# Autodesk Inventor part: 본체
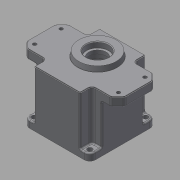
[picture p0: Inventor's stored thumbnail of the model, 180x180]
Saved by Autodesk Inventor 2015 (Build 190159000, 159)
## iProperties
Created: 2016-02
Part Number: 본체
Material: Generic
Document SubType Name: Modeling
Designer: Administrator
Density: 1 g/cm^3
Appearance: Default
Mass: 323.597 g
Surface Area: 761.323 cm^2
Volume: 323.597 cm^3
Author: Administrator
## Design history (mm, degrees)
sketch "Sketch1"
  geometry: L1 (47, -47)-(-47, -47); L2 (-47, -47)-(-47, 47); L3 (-47, 47)-(47, 47); L4 (47, 47)-(47, -47); L5 (47, -47)-(-47, 47); L6 (-47, -47)-(47, 47); 1 further point
  constraints: 12 end point, 2 midpoint, 2 parallel, 1 horizontal, 1 perpendicular
  dimensions: "d0" = 94 distance of L2.end L3.end; "d1" = 94 distance of L3.end L1.start
extrude "Extrusion1" new body sketch "Sketch1" distance "d2" = 67; taper "d3" = 0 deg
fillet "Fillet1" dims "d4" = 8
sketch "Sketch2"
  geometry: L1 (70, -30)-(33, -30); L2 (-70, -30)-(-70, 30); L3 (-70, 30)-(-33, 30); L4 (70, 30)-(70, -30); L5 (70, -30)-(-70, 30); L6 (-70, -30)-(70, 30); L7 (33, -47)-(-33, -47); L8 (-33, -47)-(-33, -30); L9 (-33, 47)-(33, 47); L10 (33, 47)-(33, 30); L11 (33, -47)-(-33, 47); L12 (-33, -47)-(33, 47); L13 (-33, 30)-(33, 30); L14 (-33, 30)-(-33, 47); L15 (-33, -30)-(-33, 30); L16 (33, -30)-(-33, -30); L17 (-33, -30)-(-70, -30); L18 (33, -30)-(33, -47); L19 (33, 30)-(33, -30); L20 (33, 30)-(70, 30); 1 further point
  constraints: 40 end point, 20 parallel, 6 perpendicular, 4 horizontal, 4 midpoint, 1 point on line
  dimensions: "d5" = 140 distance of L2.end L4.start; "d6" = 60 distance of L2.start L2.end; "d7" = 66 distance between parallel lines of L8 L10; "d8" = 94 distance between parallel lines of L7 L9
extrude "Extrusion2" join sketch "Sketch2" distance "d9" = 13; taper "d10" = 0 deg
sketch "Sketch3"
  geometry: L1 (-33, 30)-(-33, 47) reference; L2 (-33, 47)-(-39, 47) reference; L3 (-47, 39)-(-47, 30) reference; L4 (-47, 30)-(-33, 30) reference; L5 (33, 30)-(47, 30) reference; L6 (47, 30)-(47, 39) reference; L7 (39, 47)-(33, 47) reference; L8 (33, 47)-(33, 30) reference; L9 (47, -30)-(33, -30) reference; L10 (33, -30)-(33, -47) reference; L11 (33, -47)-(39, -47) reference; L12 (47, -39)-(47, -30) reference; L13 (-33, -47)-(-33, -30) reference; L14 (-33, -30)-(-47, -30) reference; L15 (-47, -30)-(-47, -39) reference; L16 (-39, -47)-(-33, -47) reference; A1 r 8 centre (-39, 39) between (-39, 47) and (-47, 39) reference; A2 r 8 centre (39, 39) between (47, 39) and (39, 47) reference; A3 r 8 centre (39, -39) between (39, -47) and (47, -39) reference; A4 r 8 centre (-39, -39) between (-47, -39) and (-39, -47) reference; 1 further point
extrude "Extrusion3" cut sketch "Sketch3" distance "d11" = 70; taper "d12" = 0 deg
sketch "Sketch4"
  geometry: C1 r 43 at (0, 0); 1 further point
  constraints: 1 centre point, 1 coincident
  dimensions: "d13" = 86 diameter of C1
extrude "Extrusion4" cut sketch "Sketch4" distance "d14" = 9; taper "d15" = 0 deg
hole "Hole1" diameter "d18" = 80; stored, may be unused: countersink angle "d22" = 90 deg, drill point angle "d24" = 0 deg; dims "d16" = 10, "d17" = 10, "d19" = 6, "d20" = 4, "d21" = 2, "d23" = 62
sketch "Sketch5"
  geometry: C1 r 28 at (0, 11); 1 further point
  constraints: 1 centre point, 1 vertical alignment
  dimensions: "d25" = 11 distance of point (0, 0) C1.centre; "d26" = 56 diameter of C1
extrude "Extrusion5" join sketch "Sketch5" distance "d27" = 7; taper "d28" = -10 deg
hole "Hole3" diameter "d40" = 32; stored, may be unused: countersink angle "d44" = 90 deg, drill point angle "d46" = 0 deg; dims "d38" = 10, "d39" = 10, "d41" = 6, "d42" = 4, "d43" = 2, "d45" = 8
sketch "Sketch8"
  geometry: A1 r 21 centre (0, 11) between (8.978, -7.984) and (-8.978, -7.984); A2 r 15 centre (0, -20) between (0, -5) and (-8.978, -7.984); A3 r 15 centre (0, -20) between (8.978, -7.984) and (0, -5); A4 r 15 centre (0, -20) between (-8.978, -7.984) and (8.978, -7.984); A5 r 21 centre (0, 11) between (-8.978, -7.984) and (8.978, -7.984); 2 further points
  constraints: 10 point on circle, 5 centre point, 2 vertical alignment, 1 coincident, 1 other
  dimensions: "d47" = 42 diameter of A1; "d48" = 20 distance of A2.centre point (0, 0); "d50" = 15 radius of A4
extrude "Extrusion6" join sketch "Sketch8" distance "d51" = 7; taper "d52" = 0 deg
hole "Hole4" diameter "d55" = 25; stored, may be unused: countersink angle "d59" = 90 deg, drill point angle "d61" = 0 deg; dims "d53" = 10, "d54" = 10, "d56" = 6, "d57" = 35, "d58" = 10, "d60" = 15
hole "Hole5" diameter "d64" = 19; stored, may be unused: countersink angle "d68" = 90 deg, drill point angle "d70" = 0 deg; dims "d62" = 10, "d63" = 10, "d65" = 6, "d66" = 22, "d67" = 7, "d69" = 8
fillet "Fillet2" dims "d71" = 1
chamfer "Chamfer1" distance "d72" = 10; stored, may be unused: second distance "d73" = 2, angle "d74" = 45 deg
sketch "Sketch9"
  geometry: A1 r 8 centre (-39, 39) between (-39, 47) and (-47, 39) reference; A2 r 8 centre (39, 39) between (47, 39) and (39, 47) reference; A3 r 8 centre (39, -39) between (39, -47) and (47, -39) reference; A4 r 8 centre (-39, -39) between (-47, -39) and (-39, -47) reference; 5 further points
  constraints: 2 horizontal alignment, 2 vertical alignment
  dimensions: "d125" = 40 horizontal distance of point (0, 0) point (-40, 40); "d126" = 80 distance of point (-40, 40) point (40, 40); "d127" = 40 horizontal distance of point (-40, 40) point (0, 0); "d128" = 80 distance of point (-40, -40) point (-40, 40)
hole "Hole6" sketch "Sketch9" at (-40, 40), (-40, -40), (40, -40), (40, 40) diameter "d75" = 7; stored, may be unused: countersink angle "d79" = 90 deg, drill point angle "d81" = 0 deg; dims "d76" = 6, "d77" = 22, "d78" = 7, "d80" = 8
sketch "Sketch10"
  geometry: 5 further points
  constraints: 2 horizontal alignment, 2 vertical alignment
  dimensions: "d82" = 120 distance of point (-60, -19) point (60, -19); "d83" = 60 horizontal distance of point (60, -19) point (0, 0); "d84" = 38 distance of point (60, 19) point (60, -19); "d85" = 19 vertical distance of point (60, -19) point (0, 0)
hole "Hole7" sketch "Sketch10" at (60, -19), (60, 19), (-60, 19), (-60, -19) diameter "d86" = 5; stored, may be unused: countersink angle "d90" = 90 deg, drill point angle "d92" = 0 deg; dims "d87" = 6, "d88" = 9, "d89" = 4, "d91" = 8
sketch "Sketch11" dims "d99" = 72
  geometry: A1 r 4 centre (36, 0) between (35.852, 3.997) and (35.852, -3.997); A2 r 3.5 centre (35.722, 7.495) between (35.852, 3.997) and (39.148, 8.214); A3 r 3.5 centre (35.722, -7.495) between (39.148, -8.214) and (35.852, -3.997); A4 r 40 centre (0, 0) between (39.148, -8.214) and (39.148, 8.214); 3 further points
  constraints: 8 point on circle, 4 centre point, 2 coincident, 2 horizontal alignment, 2 tangent, 7 other
  dimensions: "d100" = 4 radius of A1; "d101" = 3.5 radius of A2; "d102" = 3.5 radius of A3
extrude "Extrusion7" join sketch "Sketch11" stored distance "d103" = 7; taper "d104" = 0 deg
mirror "Mirror1"
sketch "Sketch12"
  geometry: A1 r 4 centre (36, 0) between (35.852, 3.997) and (35.852, -3.997) reference; A2 r 4 centre (-36, 0) between (-35.852, -3.997) and (-35.852, 3.997) reference; 3 further points
  constraints: 2 coincident
hole "Hole8" sketch "Sketch12" at (36, 0), (-36, 0) diameter "d105" = 3.242; stored, may be unused: countersink angle "d109" = 90 deg, drill point angle "d111" = 118 deg; dims "d106" = 7, "d107" = 9, "d108" = 4, "d110" = 9
sketch "Sketch13" dims "d0" = 94, "d1" = 94
  geometry: L1 (0, 0)-(78, 0) reference; 3 further points
  constraints: 1 midpoint, 1 vertical alignment, 1 other
  dimensions: "d112" = 40 distance of point (39, 0) point (39, -40)
emboss "Emboss1" sketch "Sketch13" dims "d0" = 94, "d1" = 94, "d113" = 0.5, "d114" = 0
fillet "Fillet3" dims "d115" = 0.3
fillet "Fillet6" dims "d121" = 3
fillet "Fillet4" dims "d119" = 5
fillet "Fillet5" dims "d120" = 2
chamfer "Chamfer2" distance "d116" = 1; stored, may be unused: second distance "d117" = 2, angle "d118" = 45 deg
sketch "Sketch14"
  geometry: L1 (33, -45)-(33, -35) reference; L2 (38, -30)-(57.929, -30) reference; L3 (68.536, -21.464)-(61.464, -28.536) reference; L4 (70, -17.929)-(70, 17.929) reference; L5 (61.464, 28.536)-(68.536, 21.464) reference; L6 (57.929, 30)-(38, 30) reference; L7 (33, 35)-(33, 45) reference; L8 (31, 47)-(-31, 47) reference; L9 (-33, 45)-(-33, 35) reference; L10 (-38, 30)-(-57.929, 30) reference; L11 (-68.536, 21.464)-(-61.464, 28.536) reference; L12 (-70, 17.929)-(-70, -17.929) reference; L13 (-61.464, -28.536)-(-68.536, -21.464) reference; L14 (-57.929, -30)-(-38, -30) reference; L15 (-33, -35)-(-33, -45) reference; L16 (-31, -47)-(31, -47) reference; L17 (-31, 46)-(31, 46); L18 (32, 45)-(32, 35); L19 (38, 29)-(57.929, 29); L20 (60.757, 27.828)-(67.828, 20.757); L21 (69, 17.929)-(69, -17.929); L22 (67.828, -20.757)-(60.757, -27.828); L23 (57.929, -29)-(38, -29); L24 (32, -35)-(32, -45); L25 (31, -46)-(-31, -46); L26 (-32, -45)-(-32, -35); L27 (-38, -29)-(-57.929, -29); L28 (-60.757, -27.828)-(-67.828, -20.757); L29 (-69, -17.929)-(-69, 17.929); L30 (-67.828, 20.757)-(-60.757, 27.828); L31 (-57.929, 29)-(-38, 29); L32 (-32, 35)-(-32, 45); C1 r 2.5 at (60, -19) reference; C2 r 2.5 at (-60, 19) reference; C3 r 2.5 at (-60, -19) reference; C4 r 2.5 at (60, 19) reference; A1 r 2 centre (31, -45) between (31, -47) and (33, -45) reference; A2 r 5 centre (38, -35) between (38, -30) and (33, -35) reference; A3 r 5 centre (57.929, -25) between (57.929, -30) and (61.464, -28.536) reference; A4 r 5 centre (65, -17.929) between (68.536, -21.464) and (70, -17.929) reference; A5 r 5 centre (65, 17.929) between (70, 17.929) and (68.536, 21.464) reference; A6 r 5 centre (57.929, 25) between (61.464, 28.536) and (57.929, 30) reference; A7 r 5 centre (38, 35) between (33, 35) and (38, 30) reference; A8 r 2 centre (31, 45) between (33, 45) and (31, 47) reference; A9 r 2 centre (-31, 45) between (-31, 47) and (-33, 45) reference; A10 r 5 centre (-38, 35) between (-38, 30) and (-33, 35) reference; A11 r 5 centre (-57.929, 25) between (-57.929, 30) and (-61.464, 28.536) reference; A12 r 5 centre (-65, 17.929) between (-68.536, 21.464) and (-70, 17.929) reference; A13 r 5 centre (-65, -17.929) between (-70, -17.929) and (-68.536, -21.464) reference; A14 r 5 centre (-57.929, -25) between (-61.464, -28.536) and (-57.929, -30) reference; A15 r 5 centre (-38, -35) between (-33, -35) and (-38, -30) reference; A16 r 2 centre (-31, -45) between (-33, -45) and (-31, -47) reference; A17 r 1 centre (31, 45) between (32, 45) and (31, 46); A18 r 6 centre (38, 35) between (32, 35) and (38, 29); A19 r 4 centre (57.929, 25) between (60.757, 27.828) and (57.929, 29); A20 r 4 centre (65, 17.929) between (69, 17.929) and (67.828, 20.757); A21 r 4 centre (65, -17.929) between (67.828, -20.757) and (69, -17.929); A22 r 4 centre (57.929, -25) between (57.929, -29) and (60.757, -27.828); A23 r 6 centre (38, -35) between (38, -29) and (32, -35); A24 r 1 centre (31, -45) between (31, -46) and (32, -45); A25 r 1 centre (-31, -45) between (-32, -45) and (-31, -46); A26 r 6 centre (-38, -35) between (-32, -35) and (-38, -29); A27 r 4 centre (-57.929, -25) between (-60.757, -27.828) and (-57.929, -29); A28 r 4 centre (-65, -17.929) between (-69, -17.929) and (-67.828, -20.757); A29 r 4 centre (-65, 17.929) between (-67.828, 20.757) and (-69, 17.929); A30 r 4 centre (-57.929, 25) between (-57.929, 29) and (-60.757, 27.828); A31 r 6 centre (-38, 35) between (-38, 29) and (-32, 35); A32 r 1 centre (-31, 45) between (-31, 46) and (-32, 45); 1 further point
  constraints: 32 end point, 32 point on circle, 16 centre point, 31 other
  dimensions: "d122" = 1 distance between parallel lines of L8 L17
extrude "Extrusion8" cut sketch "Sketch14" distance "d123" = 1; taper "d124" = 0 deg
body "Solid1"
node "Projected Loop1"
node "Projected Loop2"
node "Projected Loop3"
node "Projected Loop4"
node "Projected Loop5"
